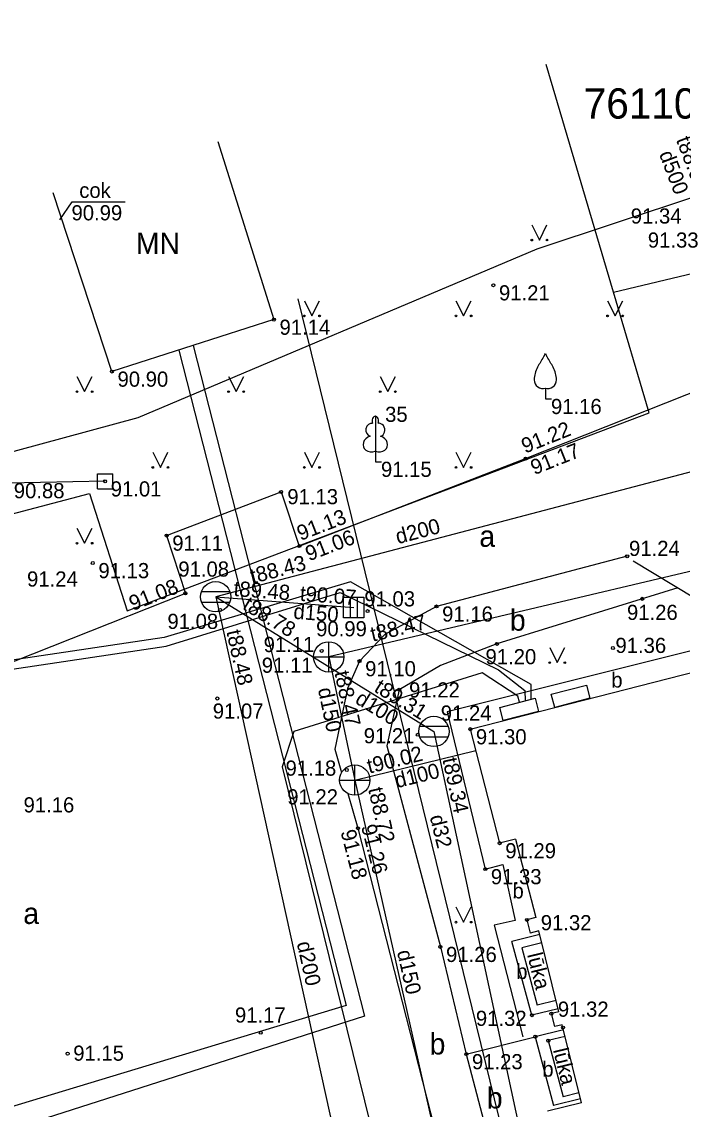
# Model space of a CAD drawing. Extents: x 634272 to 634544, y 247463 to 247653.
# Drawn here: x 634375.43 to 634397.21, y 247573.83 to 247609.7 of the extents above; entities that cross this region are included whole.
import ezdxf

# ---------------------------------------------------------------- set-up
doc = ezdxf.new("R2010")
doc.units = 0
for name, color, linetype in [('BUVE_BDET_####_####_#', 7, 'Continuous'), ('BUVE_BDET_####_TKST_#', 7, 'Continuous'), ('BUVE_COKL_####_####_#', 7, 'Continuous'), ('BUVE_EKAS_####_####_#', 7, 'Continuous'), ('BUVE_EKAS_RAKS_TKST_#', 7, 'Continuous'), ('CELI_CAPM_####_####_#', 7, 'Continuous'), ('CELI_CMAL_####_####_#', 7, 'Continuous'), ('CELI_CSEG_####_TKST_#', 7, 'Continuous'), ('ELEK_ELEM_####_####_#', 7, 'Continuous'), ('ELEK_VADP_ZSPR_####_#', 7, 'Continuous'), ('LKAN_ELEM_####_####_#', 7, 'Continuous'), ('LKAN_ELEM_PAST_TKST_#', 7, 'Continuous'), ('LKAN_VADP_PAST_####_#', 7, 'Continuous'), ('LKAN_VADP_PAST_TKST_#', 7, 'Continuous'), ('NORB_ELEM_####_####_#', 7, 'Continuous'), ('NORB_ZOGS_SBST_####_#', 7, 'Continuous'), ('RAMI_UZMR_####_####_#', 7, 'Continuous'), ('RELJ_AATZ_####_TKST_#', 7, 'Continuous'), ('RELJ_ELEM_####_####_#', 7, 'Continuous'), ('ROBZ_KADS_####_TKST_#', 7, 'Continuous'), ('ROBZ_UZMR_####_####_#', 7, 'Continuous'), ('SKAN_ELEM_####_####_#', 7, 'Continuous'), ('SKAN_ELEM_PAST_TKST_#', 7, 'Continuous'), ('SKAN_VADP_PAST_####_#', 7, 'Continuous'), ('SKAN_VADP_PAST_TKST_#', 7, 'Continuous'), ('TERT_DIAM_####_TKST_#', 7, 'Continuous'), ('TERT_ELEM_####_####_#', 7, 'Continuous'), ('UDTK_VADP_NEDR_####_#', 7, 'Continuous'), ('UDTK_VADP_UDEN_####_#', 7, 'Continuous'), ('UDTK_VADP_UDEN_TKST_#', 7, 'Continuous')]:
    doc.layers.add(name, color=color, linetype=linetype)

msp = doc.modelspace()

# ---------------------------------------------------------------- linework, layer by layer
at = {"layer": 'BUVE_BDET_####_####_#'}
for p, q in [((634392.518, 247579.592), (634391.591, 247579.364)), ((634392.586, 247579.314), (634391.924, 247579.151)), ((634393.054, 247577.416), (634392.428, 247577.262)), ((634393.121, 247577.145), (634392.254, 247576.931)), ((634393.293, 247576.449), (634392.366, 247576.221)), ((634393.347, 247576.227), (634392.795, 247576.091)), ((634393.854, 247574.171), (634392.966, 247573.952)), ((634393.806, 247574.369), (634393.289, 247574.241))]:
    msp.add_line(p, q, dxfattribs=at)
for points in [[(634401.024, 247589.834), (634389.457, 247586.939), (634390.714, 247581.751), (634391.293, 247581.906), (634391.704, 247580.059), (634391.004, 247579.905), (634391.958, 247576.222)], [(634392.254, 247576.931), (634391.591, 247579.364)], [(634391.924, 247579.151), (634392.428, 247577.262)], [(634392.366, 247576.221), (634392.966, 247573.952)], [(634392.795, 247576.091), (634393.289, 247574.241)]]:
    msp.add_lwpolyline(points, dxfattribs=at)
at = {"layer": 'BUVE_COKL_####_####_#'}
msp.add_lwpolyline([(634376.684, 247603.163), (634377.089, 247603.763), (634378.842, 247603.763)], dxfattribs=at)
at = {"layer": 'BUVE_EKAS_####_####_#'}
for p, q in [((634391.713, 247582.741), (634391.19, 247582.606)), ((634391.713, 247582.741), (634392.381, 247580.152)), ((634392.381, 247580.152), (634392.088, 247580.076)), ((634392.487, 247579.716), (634392.201, 247579.642)), ((634393.146, 247577.043), (634392.897, 247576.982)), ((634393.008, 247576.557), (634392.897, 247576.982)), ((634393.251, 247576.617), (634393.008, 247576.557)), ((634393.887, 247574.04), (634392.768, 247573.764))]:
    msp.add_line(p, q, dxfattribs=at)
for points in [[(634381.89, 247605.748), (634383.744, 247599.875), (634378.401, 247598.163), (634376.461, 247604.058)], [(634390.22, 247586.366), (634400.481, 247588.996)], [(634390.22, 247586.366), (634391.19, 247582.606)], [(634392.088, 247580.076), (634392.201, 247579.642)], [(634393.146, 247577.043), (634392.487, 247579.716)], [(634393.887, 247574.04), (634393.251, 247576.617)]]:
    msp.add_lwpolyline(points, dxfattribs=at)
at = {"layer": 'CELI_CAPM_####_####_#'}
for points in [[(634380.207, 247592.753), (634383.979, 247594.191), (634384.583, 247592.406), (634392.046, 247595.29), (634400.663, 247598.72), (634399.516, 247601.947), (634408.658, 247604.045)], [(634395.396, 247592.069), (634389.107, 247590.415), (634387.404, 247589.488), (634386.568, 247588.611), (634386.174, 247587.703), (634385.751, 247585.703), (634385.978, 247584.933)], [(634395.598, 247591.923), (634397.613, 247590.703), (634397.795, 247590.369), (634398.265, 247589.164), (634398.489, 247588.485)], [(634380.824, 247590.847), (634373.276, 247587.854), (634363.359, 247585.148)], [(634386.18, 247584.245), (634386.517, 247583.098), (634389.042, 247573.196), (634391.897, 247562.219), (634393.7, 247555.164), (634394.221, 247554.237), (634394.857, 247553.225), (634395.836, 247552.623), (634399.496, 247551.073), (634400.928, 247550.806), (634417.097, 247555.253), (634426.457, 247557.809), (634427.052, 247555.379), (634437.491, 247558.047), (634462.278, 247564.311)], [(634390.091, 247575.648), (634392.366, 247576.221)]]:
    msp.add_lwpolyline(points, dxfattribs=at)
at = {"layer": 'CELI_CMAL_####_####_#'}
for points in [[(634380.207, 247592.753), (634380.824, 247590.847)], [(634397.071, 247591.031), (634391.102, 247589.18), (634389.241, 247588.463), (634387.877, 247587.668), (634387.466, 247585.812), (634389.236, 247579.186), (634390.091, 247575.648), (634392.378, 247566.891), (634395.219, 247556.093), (634395.631, 247554.043), (634396.02, 247552.545)]]:
    msp.add_lwpolyline(points, dxfattribs=at)
at = {"layer": 'ELEK_ELEM_####_####_#'}
for points in [[(634392.892, 247587.519), (634394.054, 247587.82), (634394.167, 247587.384), (634393.005, 247587.083)], [(634391.194, 247587.086), (634392.356, 247587.387), (634392.468, 247586.952), (634391.307, 247586.651)]]:
    msp.add_lwpolyline(points, close=True, dxfattribs=at)
at = {"layer": 'ELEK_VADP_ZSPR_####_#'}
for points in [[(634392.231, 247587.355), (634392.234, 247587.84), (634386.266, 247591.23), (634380.125, 247589.395), (634354.078, 247585.508), (634351.746, 247586.285), (634342.99, 247584.518)], [(634343.193, 247584.255), (634351.727, 247585.977), (634354.051, 247585.199), (634380.191, 247589.102), (634385.926, 247590.879), (634391.152, 247588.32), (634392.016, 247587.645), (634392.036, 247587.305)], [(634391.846, 247587.255), (634391.785, 247587.453), (634390.617, 247588.23), (634384.398, 247586.285), (634384.012, 247585.121), (634391.398, 247555.188), (634394.49, 247540.075)]]:
    msp.add_lwpolyline(points, dxfattribs=at)
at = {"layer": 'LKAN_ELEM_####_####_#'}
for p, q in [((634381.356, 247590.908), (634382.292, 247590.908)), ((634386.265, 247590.719), (634386.265, 247590.044)), ((634386.49, 247590.719), (634386.49, 247590.044)), ((634381.356, 247590.558), (634382.292, 247590.558)), ((634388.553, 247586.465), (634389.489, 247586.465)), ((634388.553, 247586.115), (634389.489, 247586.115))]:
    msp.add_line(p, q, dxfattribs=at)
msp.add_lwpolyline([(634386.04, 247590.719), (634386.715, 247590.719), (634386.715, 247590.044), (634386.04, 247590.044)], close=True, dxfattribs=at)
for centre in [(634381.824, 247590.733), (634389.021, 247586.29)]:
    msp.add_circle(centre, 0.5, dxfattribs=at)
at = {"layer": 'LKAN_VADP_PAST_####_#'}
for p, q in [((634381.824, 247590.733), (634386.378, 247590.381)), ((634381.824, 247590.733), (634387.691, 247564.135)), ((634381.824, 247590.733), (634389.021, 247586.29)), ((634389.021, 247586.29), (634394.034, 247562.981))]:
    msp.add_line(p, q, dxfattribs=at)
msp.add_lwpolyline([(634400.101, 247595.54), (634381.824, 247590.733)], dxfattribs=at)
at = {"layer": 'NORB_ELEM_####_####_#'}
for p, q in [((634377.927, 247594.292), (634377.927, 247594.792)), ((634377.927, 247594.792), (634378.427, 247594.792)), ((634378.427, 247594.292), (634378.427, 247594.792)), ((634377.927, 247594.292), (634378.427, 247594.292))]:
    msp.add_line(p, q, dxfattribs=at)
msp.add_circle((634378.177, 247594.542), 0.0504, dxfattribs=at)
at = {"layer": 'NORB_ZOGS_SBST_####_#'}
msp.add_lwpolyline([(634378.177, 247594.542), (634374.98, 247594.484), (634368.742, 247592.493), (634356.291, 247588.561)], dxfattribs=at)
at = {"layer": 'RAMI_UZMR_####_####_#'}
msp.add_lwpolyline([(634357.63, 247590.775), (634379.264, 247596.642), (634392.424, 247602.216), (634402.994, 247605.715), (634421.735, 247609.504), (634423.082, 247609.702), (634425.783, 247608.304), (634427.755, 247600.855), (634433.048, 247602.581), (634454.806, 247608.92), (634459.819, 247587.798), (634462.766, 247575.147), (634466.614, 247558.36), (634469.076, 247546.545)], dxfattribs=at)
at = {"layer": 'RELJ_ELEM_####_####_#'}
for centre in [(634390.982, 247601.01), (634383.744, 247599.875), (634378.401, 247598.163), (634392.046, 247595.29), (634378.177, 247594.542), (634383.979, 247594.191), (634380.207, 247592.753), (634384.583, 247592.406), (634395.396, 247592.069), (634377.771, 247591.847), (634380.824, 247590.847), (634395.893, 247590.666), (634381.969, 247590.296), (634386.833, 247590.261), (634389.107, 247590.415), (634385.321, 247588.948), (634391.102, 247589.18), (634394.925, 247589.043), (634386.568, 247588.611), (634387.877, 247587.668), (634381.878, 247587.378), (634390.22, 247586.366), (634388.489, 247586.181), (634386.147, 247585.02), (634386.517, 247583.098), (634391.19, 247582.606), (634390.714, 247581.751), (634392.088, 247580.076), (634389.236, 247579.186), (634392.254, 247576.931), (634392.897, 247576.982), (634383.313, 247576.351), (634393.282, 247576.524), (634392.366, 247576.221), (634392.795, 247576.091), (634376.941, 247575.663), (634390.091, 247575.648)]:
    msp.add_circle(centre, 0.05, dxfattribs=at)
at = {"layer": 'ROBZ_UZMR_####_####_#'}
for points in [[(634394.943, 247600.778), (634392.725, 247608.287)], [(634394.943, 247600.778), (634404.114, 247602.967)], [(634396.12, 247596.804), (634394.943, 247600.778)], [(634378.906, 247590.272), (634396.12, 247596.804)], [(634351.357, 247587.202), (634377.661, 247594.14)], [(634377.661, 247594.14), (634378.906, 247590.272)]]:
    msp.add_lwpolyline(points, dxfattribs=at)
at = {"layer": 'SKAN_ELEM_####_####_#'}
for p, q in [((634385.552, 247588.251), (634385.552, 247589.251)), ((634385.052, 247588.751), (634386.052, 247588.751)), ((634386.413, 247584.187), (634386.413, 247585.187)), ((634385.913, 247584.687), (634386.913, 247584.687))]:
    msp.add_line(p, q, dxfattribs=at)
for centre in [(634385.552, 247588.751), (634386.413, 247584.687)]:
    msp.add_circle(centre, 0.5, dxfattribs=at)
at = {"layer": 'SKAN_VADP_PAST_####_#'}
for p, q in [((634405.576, 247593.489), (634385.552, 247588.751)), ((634385.552, 247588.751), (634386.413, 247584.687)), ((634386.413, 247584.687), (634390.402, 247585.661)), ((634386.413, 247584.687), (634390.021, 247568.662))]:
    msp.add_line(p, q, dxfattribs=at)
at = {"layer": 'TERT_ELEM_####_####_#'}
for p, q in [((634392.25, 247603), (634392.5, 247602.5)), ((634392.5, 247602.5), (634392.75, 247603)), ((634384.75, 247600.5), (634385, 247600)), ((634385, 247600), (634385.25, 247600.5)), ((634389.75, 247600.5), (634390, 247600)), ((634390, 247600), (634390.25, 247600.5)), ((634394.75, 247600.5), (634395, 247600)), ((634395, 247600), (634395.25, 247600.5)), ((634377.25, 247598), (634377.5, 247597.5)), ((634377.5, 247597.5), (634377.75, 247598)), ((634382.25, 247598), (634382.5, 247597.5)), ((634382.5, 247597.5), (634382.75, 247598)), ((634387.25, 247598), (634387.5, 247597.5)), ((634387.5, 247597.5), (634387.75, 247598)), ((634392.697, 247597.613), (634392.697, 247597.261)), ((634392.697, 247597.261), (634392.897, 247597.261)), ((634379.75, 247595.5), (634380, 247595)), ((634380, 247595), (634380.25, 247595.5)), ((634384.75, 247595.5), (634385, 247595)), ((634385, 247595), (634385.25, 247595.5)), ((634387.09, 247595.535), (634387.09, 247595.188)), ((634389.75, 247595.5), (634390, 247595)), ((634390, 247595), (634390.25, 247595.5)), ((634387.09, 247595.188), (634387.29, 247595.188)), ((634377.25, 247593), (634377.5, 247592.5)), ((634377.5, 247592.5), (634377.75, 247593)), ((634392.841, 247589.061), (634393.091, 247588.561)), ((634393.091, 247588.561), (634393.341, 247589.061)), ((634389.75, 247580.5), (634390, 247580)), ((634390, 247580), (634390.25, 247580.5))]:
    msp.add_line(p, q, dxfattribs=at)
for points in [[(634387.09, 247596.688), (634387.09, 247595.535)], [(634387.18, 247596.456), (634387.179, 247596.457)]]:
    msp.add_lwpolyline(points, dxfattribs=at)
for centre, radius in [((634392.25, 247602.5), 0.028), ((634392.75, 247602.5), 0.0263), ((634384.75, 247600), 0.028), ((634385.25, 247600), 0.0263), ((634389.75, 247600), 0.028), ((634390.25, 247600), 0.0263), ((634394.75, 247600), 0.028), ((634395.25, 247600), 0.0263), ((634377.25, 247597.5), 0.028), ((634377.75, 247597.5), 0.0263), ((634382.25, 247597.5), 0.028), ((634382.75, 247597.5), 0.0263), ((634387.25, 247597.5), 0.028), ((634387.75, 247597.5), 0.0263), ((634379.75, 247595), 0.028), ((634380.25, 247595), 0.0263), ((634384.75, 247595), 0.028), ((634385.25, 247595), 0.0263), ((634389.75, 247595), 0.028), ((634390.25, 247595), 0.0263), ((634377.25, 247592.5), 0.028), ((634377.75, 247592.5), 0.0263), ((634392.841, 247588.561), 0.028), ((634393.341, 247588.561), 0.0263), ((634389.75, 247580), 0.028), ((634390.25, 247580), 0.0263)]:
    msp.add_circle(centre, radius, dxfattribs=at)
for centre, radius, start, end in [((634405.322, 247590.865), 14.88, 148.4844, 149.9901), ((634392.28, 247598.899), 0.439, 324.3837, 341.712), ((634393.114, 247598.899), 0.439, 198.288, 215.6163), ((634380.072, 247590.865), 14.88, 30.0099, 31.5156), ((634393.221, 247597.886), 0.89, 151.757, 179.9138), ((634392.173, 247597.886), 0.89, 0.0862, 28.243), ((634392.621, 247597.892), 0.29, 181.0782, 285.2823), ((634392.773, 247597.892), 0.29, 254.7177, 358.9218)]:
    msp.add_arc(centre, radius, start, end, dxfattribs=at)
for centre, major_axis, ratio, start_param, end_param in [((634386.962, 247596.243), (-0.039, -0.212), 0.861323, 3.141593, 6.283185), ((634387.09, 247596.538), (0, -0.15), 0.707107, 3.14537, 5.287485), ((634387.09, 247596.538), (0, -0.15), 0.707107, 0.995701, 3.137816), ((634387.218, 247596.243), (0.039, -0.212), 0.861323, 0, 3.141593), ((634387, 247595.781), (0.307, 0.095), 0.814445, 1.570796, 4.752015), ((634387.18, 247595.781), (-0.307, 0.095), 0.814445, 1.531171, 4.712389)]:
    msp.add_ellipse(centre, major_axis=major_axis, ratio=ratio, start_param=start_param, end_param=end_param, dxfattribs=at)
at = {"layer": 'UDTK_VADP_NEDR_####_#'}
for points in [[(634381.084, 247599.023), (634386.736, 247576.903), (634349.56, 247564.99), (634353.161, 247551.069), (634367.117, 247543.476), (634370.735, 247530.054)], [(634380.607, 247598.87), (634386.132, 247577.25), (634361, 247569.644)]]:
    msp.add_lwpolyline(points, dxfattribs=at)
at = {"layer": 'UDTK_VADP_UDEN_####_#'}
msp.add_lwpolyline([(634384.535, 247600.557), (634392.34, 247568.756), (634395.036, 247569.467)], dxfattribs=at)

# ---------------------------------------------------------------- texts
at = {"layer": 'BUVE_BDET_####_TKST_#'}
for p in [(634394.872, 247587.739), (634391.613, 247580.783), (634391.737, 247578.122), (634392.597, 247574.904)]:
    msp.add_text('b', height=0.5, dxfattribs=at).set_placement(p)
for p in [(634392.094, 247578.93), (634392.947, 247575.784)]:
    msp.add_text('lūka', height=0.5, rotation=283.8471, dxfattribs=at).set_placement(p)
at = {"layer": 'BUVE_COKL_####_####_#'}
for s, p in [('cok', (634377.325, 247603.891)), (' 90.99', (634376.883, 247603.151))]:
    msp.add_text(s, height=0.5, dxfattribs=at).set_placement(p)
at = {"layer": 'BUVE_EKAS_RAKS_TKST_#'}
msp.add_text('MN', height=0.7, dxfattribs=at).set_placement((634379.192, 247602.043))
at = {"layer": 'CELI_CSEG_####_TKST_#'}
for s, p in [('a', (634390.52, 247592.381)), ('b', (634391.528, 247589.614)), ('a', (634375.479, 247579.941)), ('b', (634388.881, 247575.634)), ('b', (634390.768, 247573.852))]:
    msp.add_text(s, height=0.7, dxfattribs=at).set_placement(p)
at = {"layer": 'LKAN_ELEM_PAST_TKST_#'}
for s, p in [(' 91.34', (634395.33, 247603.045)), (' 91.08', (634380.407, 247591.398)), (' 90.99', (634384.951, 247589.429)), (' 91.24', (634389.063, 247586.648))]:
    msp.add_text(s, height=0.5, dxfattribs=at).set_placement(p)
at = {"layer": 'LKAN_VADP_PAST_TKST_#'}
for s, rotation, p in [('t88.02', 290.9181, (634397, 247605.811)), ('d500', 290.9181, (634396.44, 247605.344)), ('d200', 14.7355, (634387.831, 247592.468)), ('t88.43', 14.7355, (634383.046, 247591.161)), ('t89.48', 355.5801, (634382.405, 247590.762)), ('t90.07', 355.5801, (634384.59, 247590.602)), ('t88.78', 328.3113, (634382.677, 247590.352)), ('d150', 355.5801, (634384.376, 247590.01)), ('t88.48', 282.4391, (634382.173, 247589.589)), ('t89.31', 328.3113, (634387.015, 247587.628)), ('d100', 328.3113, (634386.388, 247587.248)), ('t89.34', 282.1376, (634389.3, 247585.372)), ('d200', 282.4391, (634384.497, 247579.312))]:
    msp.add_text(s, height=0.5, rotation=rotation, dxfattribs=at).set_placement(p)
at = {"layer": 'RELJ_AATZ_####_TKST_#'}
for s, p in [(' 91.33', (634395.892, 247602.251)), (' 91.21', (634390.982, 247600.51)), (' 91.14', (634383.744, 247599.375)), (' 90.90', (634378.401, 247597.663)), (' 91.16', (634392.697, 247596.761)), (' 91.15', (634387.09, 247594.688)), (' 90.88', (634374.98, 247593.984)), (' 91.01', (634378.177, 247594.042)), (' 91.13', (634384.001, 247593.787)), (' 91.11', (634380.207, 247592.253)), (' 91.24', (634395.271, 247592.08)), (' 91.13', (634377.771, 247591.347)), (' 91.24', (634375.417, 247591.07)), (' 91.03', (634386.541, 247590.416)), (' 91.16', (634389.107, 247589.915)), (' 91.26', (634395.204, 247589.97)), (' 91.08', (634380.047, 247589.673)), (' 91.11', (634383.22, 247588.908)), (' 91.36', (634394.823, 247588.88)), (' 91.20', (634390.538, 247588.508)), (' 91.10', (634386.568, 247588.111)), (' 91.22', (634388.017, 247587.411)), (' 91.07', (634381.543, 247586.714)), (' 91.21', (634386.521, 247585.9)), (' 91.30', (634390.22, 247585.866)), (' 91.18', (634383.943, 247584.832)), (' 91.16', (634375.302, 247583.619)), (' 91.29', (634391.19, 247582.106)), (' 91.33', (634390.714, 247581.251)), (' 91.32', (634392.36, 247579.733)), (' 91.26', (634389.236, 247578.686)), (' 91.17', (634382.275, 247576.687)), (' 91.32', (634390.221, 247576.578)), (' 91.32', (634392.925, 247576.88)), (' 91.15', (634376.941, 247575.429)), (' 91.23', (634390.091, 247575.148))]:
    msp.add_text(s, height=0.5, dxfattribs=at).set_placement(p)
for s, rotation, p in [(' 91.22', 21.705, (634391.858, 247595.386)), (' 91.17', 21.705, (634392.161, 247594.675)), (' 91.13', 21.1285, (634384.449, 247592.508)), (' 91.06', 21.1285, (634384.728, 247591.833)), (' 91.08', 21.6298, (634378.916, 247590.192)), (' 91.26', 284.3055, (634386.571, 247583.339)), (' 91.18', 284.3055, (634385.894, 247583.165))]:
    msp.add_text(s, height=0.5, rotation=rotation, dxfattribs=at).set_placement(p)
at = {"layer": 'ROBZ_KADS_####_TKST_#'}
msp.add_text('76110040602', height=1, dxfattribs=at).set_placement((634393.963, 247606.507))
at = {"layer": 'SKAN_ELEM_PAST_TKST_#'}
for s, p in [(' 91.11', (634383.16, 247588.226)), (' 91.22', (634383.999, 247583.884))]:
    msp.add_text(s, height=0.5, dxfattribs=at).set_placement(p)
at = {"layer": 'SKAN_VADP_PAST_TKST_#'}
for s, rotation, p in [('t88.47', 13.3123, (634386.999, 247589.248)), ('t88.47', 281.9618, (634385.74, 247588.238)), ('d150', 281.9618, (634385.193, 247587.687)), ('t90.02', 13.7259, (634386.886, 247584.898)), ('d100', 13.7259, (634387.803, 247584.42)), ('t88.72', 282.6885, (634386.851, 247584.392)), ('d150', 282.6885, (634387.801, 247579.028))]:
    msp.add_text(s, height=0.5, rotation=rotation, dxfattribs=at).set_placement(p)
at = {"layer": 'TERT_DIAM_####_TKST_#'}
msp.add_text('35', height=0.5, dxfattribs=at).set_placement((634387.412, 247596.503))
at = {"layer": 'UDTK_VADP_UDEN_TKST_#'}
msp.add_text('d32', height=0.5, rotation=283.79, dxfattribs=at).set_placement((634388.881, 247583.481))

doc.saveas('drawing.dxf')
